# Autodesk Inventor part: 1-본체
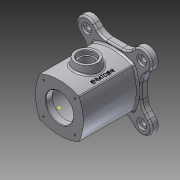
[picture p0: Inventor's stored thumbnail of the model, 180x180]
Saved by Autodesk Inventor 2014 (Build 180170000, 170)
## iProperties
Created: 2016-05
Part Number: 1-본체
Material: 알루미늄 6061
Document SubType Name: Modeling
Designer: HGY
Density: 2.71 g/cm^3
Appearance: 알루미늄 - 평지
Mass: 1114.45 g
Surface Area: 865.598 cm^2
Volume: 411.237 cm^3
Author: HGY
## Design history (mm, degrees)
sketch "스케치1"
  geometry: L1 (35.355, -35.355)-(-35.355, -35.355); L2 (-35.355, -35.355)-(-35.355, 35.355); L3 (-35.355, 35.355)-(35.355, 35.355); L4 (35.355, 35.355)-(35.355, -35.355); L5 (35.355, -35.355)-(-35.355, 35.355); L6 (-35.355, -35.355)-(35.355, 35.355); A1 r 85.579 centre (0, -42.579) between (35.355, 35.355) and (-35.355, 35.355); A2 r 85.579 centre (42.579, 0) between (-35.355, 35.355) and (-35.355, -35.355); A3 r 85.579 centre (0, 42.579) between (-35.355, -35.355) and (35.355, -35.355); A4 r 85.579 centre (-42.579, 0) between (35.355, -35.355) and (35.355, 35.355); 1 further point
  constraints: 12 end point, 8 point on circle, 4 centre point, 3 equal radius, 2 midpoint, 2 parallel, 2 perpendicular, 1 horizontal
  dimensions: "d2" = 100 distance of L1.end L3.end; "d4" = 86 dimension on A3 A1
extrude "돌출1" new body sketch "스케치1" distance "d5" = 110; taper "d6" = 0 deg
sketch "스케치2" dims "d70" = 45 deg
  geometry: L1 (49.497, -49.497)-(-49.497, 49.497); L2 (62.225, -36.77)-(-36.77, 62.225); L3 (-62.225, 36.77)-(36.77, -62.225); L4 (49, 49)-(-49, 49); L5 (-49, 49)-(-49, -49); L6 (-49, -49)-(49, -49); L7 (49, -49)-(49, 49); L8 (49, 49)-(-49, -49); L9 (-49, 49)-(49, -49); L10 (49.497, 49.497)-(-49.497, -49.497); L11 (36.77, 62.225)-(-62.225, -36.77); L12 (-36.77, -62.225)-(62.225, 36.77); A1 r 18 centre (49.497, -49.497) between (36.77, -62.225) and (62.225, -36.77); A2 r 18 centre (-49.497, 49.497) between (-36.77, 62.225) and (-62.225, 36.77); A3 r 70 centre (0, 0) between (49.497, -49.497) and (-49.497, -49.497); A4 r 18 centre (49.497, 49.497) between (62.225, 36.77) and (36.77, 62.225); A5 r 18 centre (-49.497, -49.497) between (-62.225, -36.77) and (-36.77, -62.225); 5 further points
  constraints: 28 end point, 10 point on circle, 8 tangent, 6 midpoint, 5 centre point, 4 parallel, 3 coincident, 2 perpendicular, 2 point on line, 1 horizontal
  dimensions: "d7" = 98 distance of L5.end L6.end; "d8" = 36 distance between parallel lines of L2 L3; "d9" = 70 radius of A3; "d10" = 36 distance between parallel lines of L11 L12 (= d8)
extrude "돌출2" join sketch "스케치2" distance "d11" = 12; taper "d12" = 0 deg
node "작업 평면1"
sketch "스케치3"
  geometry: C1 r 20 at (0, 49); 1 further point
  constraints: 1 centre point, 1 vertical alignment
  dimensions: "d14" = 40 diameter of C1; "d15" = 49 distance of point (0, 0) C1.centre
extrude "돌출3" join sketch "스케치3" stored distance "d16" = 12; taper "d17" = 10 deg
sketch "스케치4"
  geometry: 1 further point
sketch "스케치5"
  geometry: L1 (-22, 0)-(132, 0) reference; L2 (0, 25)-(12, 25); L3 (12, 25)-(12, 0); L4 (12, 0)-(0, 0); L5 (0, 0)-(0, 25); L6 (12, 0)-(98, 0); L7 (98, 0)-(98, 35); L8 (98, 35)-(12, 35); L9 (12, 35)-(12, 0); L10 (98, 0)-(110, 0); L11 (110, 0)-(110, 25); L12 (110, 25)-(98, 25); L13 (98, 25)-(98, 0); L14 (0, -35.355)-(0, 35.355) reference; L15 (110, -23.544)-(110, 23.544) reference; 1 further point
  constraints: 24 end point, 6 parallel, 3 horizontal, 3 perpendicular, 2 collinear, 1 midpoint, 1 point on line
  dimensions: "d18" = 70 diameter of L8 L1; "d19" = 50 diameter of L2 L1; "d20" = 50 diameter of L12 L1; "d21" = 86 distance of L7.end L8.end; "d22" = 12 distance of L2.start L2.end
revolve "회전1" sketch "스케치5" stored, may be unused: angle "d23" = 90 deg
hole "구멍1" diameter "d26" = 25; stored, may be unused: countersink angle "d30" = 90 deg, drill point angle "d32" = 118 deg; dims "d24" = 10, "d25" = 10, "d27" = 6, "d28" = 30, "d29" = 8, "d31" = 8
sketch "스케치6"
  geometry: L1 (0, 0)-(28.284, -28.284); L2 (-94.496, 0)-(94.496, 0) reference
  constraints: 2 end point
  dimensions: "d33" = 45 deg angle of L2 L1; "d34" = 40 distance of L1.start L1.end
hole "구멍2" sketch "스케치6" at (28.284, -28.284) diameter "d35" = 3.242; stored, may be unused: countersink angle "d39" = 90 deg, drill point angle "d41" = 118 deg; dims "d36" = 7, "d37" = 30, "d38" = 8, "d40" = 10
hole "구멍3" diameter "d47" = 10; stored, may be unused: countersink angle "d51" = 90 deg, drill point angle "d53" = 118 deg; dims "d45" = 10, "d46" = 10, "d48" = 7, "d49" = 18, "d50" = 4, "d52" = 10
fillet "모깎기1" dims "d57" = 25
fillet "모깎기2" dims "d58" = 3
fillet "모깎기3" dims "d59" = 3
fillet "모깎기4" dims "d60" = 3
fillet "모깎기5" dims "d61" = 3
chamfer "모따기1" distance "d62" = 1; stored, may be unused: second distance "d63" = 2, angle "d64" = 45 deg
node "작업 평면2"
sketch "스케치8"
  geometry: L1 (0, 0)-(29, 0); L2 (29, 0)-(29, 49); L3 (29, 49)-(0, 49); L4 (0, 49)-(0, 0); 1 further point
  constraints: 8 end point, 2 parallel, 1 coincident, 1 horizontal, 1 perpendicular, 1 other
  dimensions: "d65" = 49 distance of L3.end L1.start; "d66" = 29 distance of L2.end L3.end
sketch "스케치9"
  geometry: L1 (0, 0)-(28.284, 28.284); L2 (-94.496, 0)-(94.496, 0) reference
  constraints: 2 end point
  dimensions: "d69" = 40 distance of L1.start L1.end; "d70" = 45 deg angle of L1 L2
hole "구멍4" sketch "스케치9" at (28.284, 28.284) diameter "d71" = 3.242; stored, may be unused: countersink angle "d75" = 90 deg, drill point angle "d77" = 118 deg; dims "d72" = 7, "d73" = 18, "d74" = 4, "d76" = 10
feature "엠보싱2" dims "d2" = 100, "d4" = 86, "d7" = 98, "d8" = 36, "d9" = 70, "d10" = 36 (= d8), "d70" = 45 deg, "d81" = 0.5, "d82" = 0
node "솔리드1"
pattern_circular "원형 패턴1" dims angle "d43" = 360 deg
pattern_circular "원형 패턴2" dims angle "d55" = 360 deg
pattern_circular "원형 패턴3" dims angle "d79" = 360 deg
other parameters: "d13" = 55
